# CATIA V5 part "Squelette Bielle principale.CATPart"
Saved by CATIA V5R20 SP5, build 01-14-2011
Part number: Squelette Bielle principale
Bounding box of the stored display mesh (mm): x -250 to -160, y -325 to 100, z -70 to 110
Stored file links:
  U:\CFAO\Thinkmotion\Squelette Bielle principale.CATPart
  U:\CFAO\Thinkmotion\Bras Articule.CATProduct
  U:\CFAO\Thinkmotion\Squelette general.CATPart
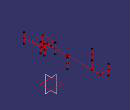
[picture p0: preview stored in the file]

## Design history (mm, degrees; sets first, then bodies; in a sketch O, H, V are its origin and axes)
Set1
  Line1: type PtPt, FirstPoint Point1, SecondPoint Point2
  Line2: type PtPt, FirstPoint Point2, SecondPoint Point3
  Line3: type PtPt, FirstPoint Point3, SecondPoint Point4
  Line4: type PtPt, FirstPoint Point5, SecondPoint Point4
  Line5: type PtPt, FirstPoint Point5, SecondPoint Point6
  Line6: type PtPt, FirstPoint Point6, SecondPoint Point7
  Line7: type PtPt, FirstPoint Point7, SecondPoint Point8
  Line8: type PtPt, FirstPoint Point6, SecondPoint Point9
  Line9: type PtPt, FirstPoint Point3, SecondPoint Point10
  Line10: type PtPt, FirstPoint Point2, SecondPoint Point11
  Line11: type PtPt, FirstPoint Point5, SecondPoint Point12
  Line12: type Normal, RefPoint Point1, RefSkin Plane2, Start -30, End 30
  Line13: type Normal, RefPoint Point11, RefSkin Plane2, Start -30, End 30
  Line14: type Normal, RefPoint Point10, RefSkin Plane2, Start -30, End 30
  Line15: type Normal, RefPoint Point4, RefSkin Plane2, Start -30, End 30
  Line16: type Normal, RefPoint Point12, RefSkin Plane2, Start -30, End 30
  Line17: type Normal, RefPoint Point9, RefSkin Plane2, Start -30, End 30
  Line18: type Normal, RefPoint Point8, RefSkin Plane2, Start -30, End 30
  Plane1: type OffsetPt, RefPlane xy-plane, RefPoint Point1
  Line19: type PtPt, FirstPoint Point10, SecondPoint Point11
  Line20: type PtPt, FirstPoint Point11, SecondPoint Point13
  Line21: type Normal, RefPoint Point13, RefSkin xy-plane, Start -30, End 30
Set2
  Point1 to Point12: linked copy from another document
  Plane2: linked copy from another document
  Point13: linked copy from another document
Body1 (main body)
